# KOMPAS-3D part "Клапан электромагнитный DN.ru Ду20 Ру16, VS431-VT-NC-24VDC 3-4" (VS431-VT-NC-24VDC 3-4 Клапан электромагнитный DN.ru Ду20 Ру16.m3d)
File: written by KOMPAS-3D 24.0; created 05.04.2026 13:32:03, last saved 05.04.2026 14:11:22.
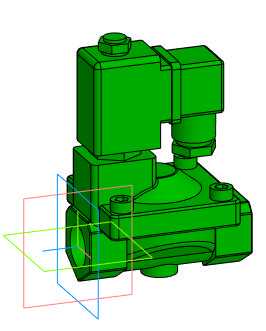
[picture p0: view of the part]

Document properties: Автор: artio; Полное имя файла: C:\Users\artio\OneDrive\Рабочий стол\Клапан электромагнитный DN.ru\VS431\VS431-VT-NC\VS431-VT-NC-24VDC\Ду20\VS431-VT-NC-24VDC 3-4 Клапан электромагнитный DN.ru Ду20 Ру16.m3d

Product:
- Body: Тело 1  | qty 1
    Масса: 1.198355
- Part/product: Клапан электромагнитный DN.ru Ду20 Ру16  | designation VS431-VT-NC-24VDC 3-4
    Масса: 0.907
    Раздел спецификации: Прочие изделия
    Примечание: D130-04755
    additional columns: ef56311e-7521-43dc-8291-0e6108b3d81d; artio; c; Шероховатость не задана; Да

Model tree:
1. Операция без истории:1

Expressions: VS431-VT-NC-24VDC 3-4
